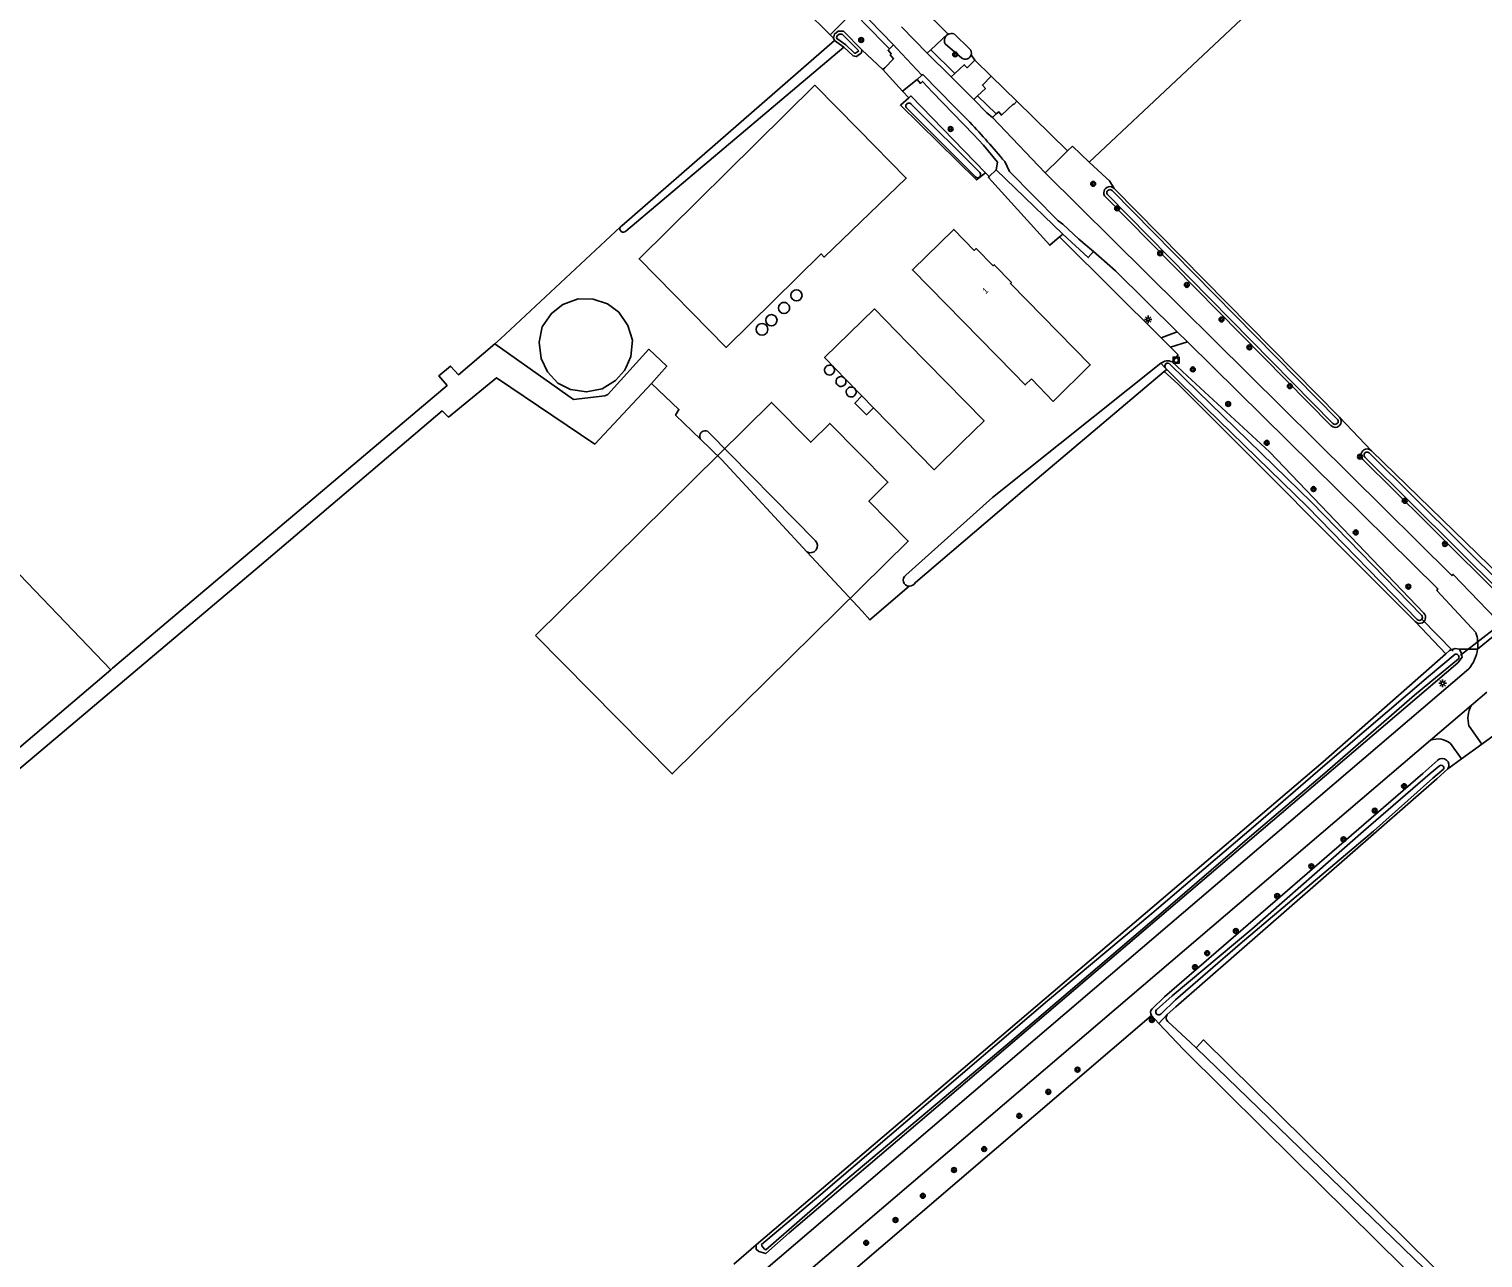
# Model space of a CAD drawing. Extents: x 141000 to 143000, y 400580 to 403500.
# Drawn here: x 142087.7 to 142326.5, y 402801.5 to 403003.4 of the extents above; entities that cross this region are included whole.
import ezdxf

# ---------------------------------------------------------------- set-up
doc = ezdxf.new("R2010")
doc.units = 0
for name, color, linetype in [('gg-afsc-erfafscheiding', 7, 'Continuous'), ('gg-anno-huisnummerreeks BGT', 7, 'Continuous'), ('gg-bbg-bijgebouw', 7, 'Continuous'), ('gg-bbg-gedigitaliseerde bijgebouw', 7, 'Continuous'), ('gg-bbg-hoofdgebouw', 7, 'Continuous'), ('gg-bbg-luifel en loopbrug', 7, 'Continuous'), ('gg-bbg-overig bouwwerk', 7, 'Continuous'), ('gg-knt-bronhoudergrens', 7, 'Continuous'), ('gg-knt-onverhard', 7, 'Continuous'), ('gg-knt-verharding', 7, 'Continuous'), ('gg-knt-verharding nz', 7, 'Continuous'), ('gg-kntw-bovenkant insteek waterloop', 7, 'Continuous'), ('gg-kntw-waterlijn', 7, 'Continuous'), ('gg-kwrk-duiker nz buis', 7, 'Continuous'), ('gt-bbg-plantopografie pand', 7, 'Continuous'), ('gt-grn-groengrens', 7, 'Continuous'), ('gt-grn-vlakafsluiter', 7, 'Continuous'), ('gt-grn-weggrens', 7, 'Continuous'), ('gt-symb-boom', 7, 'Continuous'), ('gt-symb-lichtmast', 7, 'Continuous'), ('gt-symb-rioolschacht', 7, 'Continuous')]:
    doc.layers.add(name, color=color, linetype=linetype)

# ---------------------------------------------------------------- blocks, each defined once
blk = doc.blocks.new('gt0-LMAST')
at = {"layer": 'gt-symb-lichtmast'}
for p, q in [((-0.18, 0.17), (-0.45, 0.44)), ((-0.01, 0.25), (-0.01, 0.62)), ((0.17, 0.17), (0.44, 0.44)), ((-0.26, 0), (-0.63, 0)), ((-0.18, -0.18), (-0.45, -0.45)), ((-0.01, -0.25), (-0.01, -0.63)), ((0.44, -0.45), (0.17, -0.18)), ((0.24, 0), (0.62, 0))]:
    blk.add_line(p, q, dxfattribs=at)
blk.add_circle((-0.01, 0), 0.25, dxfattribs=at)
blk = doc.blocks.new('gt0-BOOM')
at = {"layer": 'gt-symb-boom'}
for radius in [0.4, 0.2]:
    blk.add_circle((0, 0), radius, dxfattribs=at)
blk = doc.blocks.new('gt0-RS')
at = {"layer": 'gt-symb-rioolschacht'}
blk.add_lwpolyline([(-0.5, -0.5), (0.5, -0.5), (0.5, 0.5), (-0.5, 0.5)], close=True, dxfattribs=at)
blk.add_circle((0, 0), 0.375, dxfattribs=at)

msp = doc.modelspace()

# ---------------------------------------------------------------- linework, layer by layer
at = {"layer": 'gg-afsc-erfafscheiding'}
for p, q in [((142227.95, 402996.74), (142224.5, 403000.01)), ((142232.21, 402992.13), (142231.16, 402993.21)), ((142245.42, 402979.18), (142244.82, 402979.8))]:
    msp.add_line(p, q, dxfattribs=at)
for points in [[(142273.63, 402952.69), (142257.5, 402968.7), (142256.97, 402969.25)], [(142275.46, 402948.72), (142276.43, 402949.86), (142275.17, 402951.14)]]:
    msp.add_lwpolyline(points, dxfattribs=at)
at = {"layer": 'gg-bbg-bijgebouw'}
msp.add_line((142224.5, 402943.13), (142226.39, 402941.2), dxfattribs=at)
for points in [[(142223.91, 402986.92), (142231.78, 402978.93), (142218.31, 402965.95), (142217.8, 402966.46), (142202.21, 402951.11), (142187.87, 402965.68), (142216.78, 402994.16), (142223.91, 402986.92)], [(142226.39, 402941.2), (142236.35, 402931), (142240.98, 402935.53), (142244.55, 402939.02), (142231.99, 402951.88), (142226.57, 402957.43), (142218.37, 402949.42), (142223.78, 402943.87), (142224.5, 402943.13)]]:
    msp.add_lwpolyline(points, dxfattribs=at)
at = {"layer": 'gg-bbg-gedigitaliseerde bijgebouw'}
for points in [[(142171.79, 402949.27), (142171.45, 402951.97), (142171.94, 402954.5), (142173.47, 402956.69), (142175.35, 402958.18), (142177.9, 402959.07), (142180.32, 402959.05), (142182.72, 402958.28), (142184.55, 402956.9), (142186.05, 402954.73), (142186.8, 402952.28), (142186.55, 402949.6), (142185.74, 402947.88)], [(142181.8, 402944.31), (142179.27, 402943.79), (142176.61, 402944.18), (142174.54, 402945.24), (142172.85, 402947.07), (142171.79, 402949.27)], [(142181.8, 402944.31), (142183.99, 402945.68), (142185.48, 402947.33), (142185.74, 402947.88)]]:
    msp.add_lwpolyline(points, dxfattribs=at)
at = {"layer": 'gg-bbg-hoofdgebouw'}
msp.add_lwpolyline([(142252.33, 402945.92), (142255.92, 402942.22), (142262.01, 402948.23), (142248.88, 402961.62), (142249.04, 402961.78), (142246.24, 402964.67), (142246.08, 402964.52), (142243.24, 402967.34), (142242.95, 402967.05), (142239.61, 402970.5), (142232.78, 402963.87), (142249.42, 402946.94), (142251.32, 402944.95), (142252.33, 402945.92)], dxfattribs=at)
at = {"layer": 'gg-bbg-luifel en loopbrug'}
msp.add_lwpolyline([(142224.5, 402943.13), (142223.33, 402941.97), (142225.22, 402940.05), (142226.39, 402941.2)], dxfattribs=at)
at = {"layer": 'gg-bbg-overig bouwwerk'}
for centre, radius, start, end in [((142213.74, 402959.65), 0.917, 135.044, 314.956), ((142213.74, 402959.65), 0.917, 315.044, 134.956), ((142211.69, 402957.57), 0.917, 135.0221, 315.0221), ((142211.69, 402957.57), 0.917, 315.0219, 135.0223), ((142209.62, 402955.57), 0.922, 135, 315), ((142209.62, 402955.57), 0.922, 315.0438, 134.9562), ((142208.08, 402954.07), 0.954, 135, 315), ((142208.08, 402954.07), 0.954, 314.9575, 135.0425), ((142219.17, 402947.38), 0.818, 93.7557, 273.8119), ((142219.17, 402947.38), 0.818, 273.7602, 93.8075), ((142221.05, 402945.5), 0.818, 93.7512, 273.8164), ((142221.05, 402945.5), 0.818, 273.8117, 93.7559), ((142222.72, 402943.78), 0.818, 138.7544, 318.8277), ((142222.72, 402943.78), 0.818, 318.781, 138.801)]:
    msp.add_arc(centre, radius, start, end, dxfattribs=at)
at = {"layer": 'gg-knt-bronhoudergrens'}
for p, q in [((142215.06, 403006.63), (142219.28, 403002.43)), ((142219.28, 403002.43), (142219.81, 403001.91)), ((142101.08, 402898.11), (142009.26, 402994.01)), ((142261.85, 402981.56), (142259.09, 402984.18)), ((142265.14, 402978.45), (142265.94, 402977.22)), ((142308.19, 402934.13), (142302.97, 402939.64)), ((142315.37, 402906.05), (142320.4, 402900.74)), ((142328.97, 402887.85), (142326.36, 402885.95)), ((142320.76, 402881.88), (142323.02, 402883.52)), ((142272.08, 402841.33), (142221.14, 402797.79)), ((142203.46, 402800.52), (142207.1, 402803.67))]:
    msp.add_line(p, q, dxfattribs=at)
for points in [[(142210.84, 403030.92), (142245.72, 403061.99), (142292.19, 403010.09), (142261.85, 402981.56)], [(142261.85, 402981.56), (142264.62, 402978.94), (142265.14, 402978.45)], [(142164.17, 402951.7), (142165.12, 402952.51), (142184.82, 402970.89)], [(142164.17, 402951.7), (142158.23, 402946.6), (142156.89, 402948.03), (142154.99, 402946.45), (142156.33, 402944.86), (142101.4, 402898.39), (142101.08, 402898.11)], [(142164.17, 402951.7), (142177.12, 402942.53), (142182.26, 402943.17), (142182.75, 402943.39), (142189.47, 402950.79), (142192.43, 402948.01), (142189.91, 402945.16)], [(142024.33, 402840.61), (142022.47, 402838.91), (142028.48, 402832.9), (142040.38, 402843.06), (142064.01, 402863.29), (142090.33, 402885.42), (142125.51, 402915.15), (142155.54, 402940.68), (142156.57, 402939.65), (142164.47, 402946.13), (142180.6, 402935.22), (142189.91, 402945.16)], [(142189.91, 402945.16), (142194.43, 402940.93), (142193.88, 402939.99), (142197.98, 402936.02)], [(142215.46, 402917.5), (142224.55, 402907.77), (142225.81, 402906.35), (142232.25, 402911.88)], [(142101.08, 402898.11), (142028.36, 402836.3), (142024.33, 402840.61)], [(142368.96, 402748.16), (142369.92, 402749.18), (142351.54, 402767.36), (142280.62, 402837.33), (142279.39, 402836.06)]]:
    msp.add_lwpolyline(points, dxfattribs=at)
at = {"layer": 'gg-knt-onverhard'}
for p, q in [((142223.1, 403006.27), (142219.28, 403002.43)), ((142323.02, 402883.52), (142326.36, 402885.95))]:
    msp.add_line(p, q, dxfattribs=at)
at = {"layer": 'gg-knt-verharding'}
for p, q in [((142223.78, 403006.91), (142229.69, 403000.79)), ((142235.23, 402999.43), (142230.98, 403003.74)), ((142239.15, 402995.54), (142235.23, 402999.43)), ((142239.73, 402996.11), (142235.81, 403000)), ((142227.95, 402996.74), (142228.27, 402997.05)), ((142231.16, 402993.21), (142227.95, 402996.74)), ((142233.58, 402995.11), (142231.16, 402993.21)), ((142242.86, 402991.82), (142239.15, 402995.54)), ((142246.56, 402989.46), (142243.46, 402992.42)), ((142254.62, 402979.79), (142245.96, 402988.85)), ((142258.27, 402983.38), (142259.09, 402984.18)), ((142246.54, 402980.26), (142245.42, 402979.18)), ((142257.52, 402969.72), (142256.97, 402969.25)), ((142266.14, 402963.68), (142276.29, 402953.67)), ((142276.29, 402953.67), (142273.63, 402952.69)), ((142275.17, 402951.14), (142273.63, 402952.69)), ((142276.29, 402953.67), (142277.97, 402952.02)), ((142277.97, 402952.02), (142275.17, 402951.14)), ((142324.18, 402898.3), (142206.08, 402797.45)), ((142324.59, 402892.27), (142327.18, 402894.49)), ((142324.23, 402888.87), (142326.36, 402885.95)), ((142209.61, 402794.18), (142317.92, 402886.59)), ((142323.02, 402883.52), (142321.19, 402886.04))]:
    msp.add_line(p, q, dxfattribs=at)
for points in [[(142229.05, 403000.17), (142224.8, 403004.45), (142223.1, 403006.27)], [(142234.34, 402995.84), (142230.24, 403000.23), (142229.69, 403000.79)], [(142235.81, 403000), (142237.64, 403001.68), (142238.61, 403002.64)], [(142228.27, 402997.05), (142229.7, 402998.51), (142229.14, 402999.14), (142229.31, 402999.35), (142228.79, 402999.92), (142229.05, 403000.17)], [(142239.73, 402996.11), (142241.3, 402997.53), (142241.8, 402997.05), (142243.04, 402998.31)], [(142242.23, 402988.08), (142239.77, 402990.55), (142234.49, 402995.93), (142234.34, 402995.84)], [(142243.46, 402992.42), (142244.77, 402993.64), (142244.3, 402994.2), (142245.74, 402995.66)], [(142246.54, 402980.26), (142246.74, 402981.56), (142244.48, 402984.31), (142242.83, 402986.08), (142236.09, 402993.04), (142234.42, 402994.79), (142234.1, 402994.47), (142233.58, 402995.11)], [(142242.86, 402991.82), (142245.01, 402989.66), (142245.96, 402988.85)], [(142246.56, 402989.46), (142247.01, 402989.78), (142247.4, 402989.27), (142249.35, 402991.08), (142249.45, 402991.01), (142249.96, 402991.53)], [(142262.53, 402966.84), (142260.14, 402968.88), (142257.5, 402971.34), (142256.73, 402971.91), (142248.73, 402979.98), (142247.95, 402981.62)], [(142254.62, 402979.79), (142256.99, 402982.13), (142258.27, 402983.38)], [(142256.97, 402969.25), (142255.35, 402967.88), (142245.27, 402979.03), (142245.42, 402979.18)], [(142330.02, 402905.09), (142321.65, 402913.8), (142321.43, 402913.61), (142254.62, 402979.79)], [(142262.53, 402966.84), (142261.67, 402965.86), (142257.52, 402969.72)], [(142266.14, 402963.68), (142263.43, 402966.08), (142262.53, 402966.84)], [(142277.97, 402952.02), (142319.13, 402911.42), (142318.96, 402911.17), (142325.38, 402904.2)]]:
    msp.add_lwpolyline(points, dxfattribs=at)
for centre, radius, start, end in [((142147.78, 402898.63), 130.08, 39.6422, 43.4452), ((142319.51, 402902.32), 6.16, 352.7594, 17.7772), ((142319.51, 402902.32), 6.16, 319.2711, 352.7448), ((142328.67, 402890.13), 4.62, 152.3265, 195.7818), ((142319.06, 402883.36), 3.42, 51.4883, 109.4163)]:
    msp.add_arc(centre, radius, start, end, dxfattribs=at)
at = {"layer": 'gg-knt-verharding nz'}
for p, q in [((142229.05, 403000.17), (142229.69, 403000.79)), ((142235.81, 403000), (142235.23, 402999.43)), ((142234.34, 402995.84), (142233.58, 402995.11)), ((142239.15, 402995.54), (142239.73, 402996.11)), ((142243.46, 402992.42), (142242.86, 402991.82)), ((142245.96, 402988.85), (142246.56, 402989.46)), ((142317.92, 402886.59), (142324.59, 402892.27))]:
    msp.add_line(p, q, dxfattribs=at)
at = {"layer": 'gg-kntw-bovenkant insteek waterloop'}
for p, q in [((142185.73, 402970.18), (142221.52, 403000.43)), ((142219.97, 403001.52), (142219.81, 403001.91)), ((142238.17, 403000.97), (142240.91, 402998.61)), ((142242.22, 403000.12), (142239.62, 403002.59)), ((142302.97, 402939.64), (142265.94, 402977.22)), ((142301.52, 402938.26), (142264.52, 402975.82)), ((142216.84, 402919.35), (142199.31, 402937.2)), ((142272.08, 402841.33), (142273.27, 402840.06))]:
    msp.add_line(p, q, dxfattribs=at)
for points in [[(142224.5, 403000.01), (142221.45, 403003.04), (142220.58, 403003.06), (142219.98, 403002.57), (142219.81, 403001.91)], [(142184.82, 402970.89), (142184.92, 402971.01), (142185.05, 402971.1), (142219.97, 403001.52)], [(142221.52, 403000.43), (142223.04, 402999), (142223.58, 402998.89), (142224.42, 402999.5), (142224.5, 403000.01)], [(142244.82, 402979.8), (142243.34, 402978.63), (142230.81, 402990.89), (142232.21, 402992.13)], [(142244.82, 402979.8), (142232.54, 402992.42), (142232.21, 402992.13)], [(142231.71, 402913.67), (142245.97, 402926.47), (142273.61, 402948.5)], [(142275.46, 402948.72), (142277.9, 402946.45), (142291.44, 402933.96), (142316.8, 402907.45)], [(142233.28, 402912.5), (142250.82, 402927.41), (142274.15, 402947.15)], [(142274.15, 402947.15), (142276.37, 402945.1), (142315.37, 402906.05)], [(142197.98, 402936.02), (142201.48, 402932.63), (142215.46, 402917.5)], [(142333.37, 402910.48), (142332.84, 402910.5), (142332.22, 402910.75), (142331.43, 402911.54), (142308.19, 402934.13)], [(142331.1, 402908.56), (142317.19, 402922.38), (142306.78, 402932.71)], [(142322.68, 402901.52), (142323.02, 402900.84), (142323.09, 402900.24), (142322.38, 402899.26), (142266.3, 402851.46), (142212.55, 402805.67), (142208.68, 402802.25), (142207.57, 402802.57), (142207.11, 402802.95), (142207.1, 402803.67)], [(142207.1, 402803.67), (142300.27, 402883.03), (142320.4, 402900.74)], [(142322.68, 402901.52), (142321.96, 402901.63), (142321.03, 402901.29), (142320.4, 402900.74)], [(142319.08, 402883.32), (142316.66, 402881.08), (142274.22, 402844.4), (142272.17, 402842.44)], [(142274.65, 402841.52), (142276.07, 402842.77), (142318.93, 402880.24), (142320.76, 402881.88)], [(142369.74, 402743.71), (142350.81, 402762.53), (142341.22, 402772.59), (142290.46, 402822.73), (142277.32, 402835.78), (142273.27, 402840.06)], [(142279.39, 402836.06), (142278.49, 402836.93), (142274.73, 402840.35)], [(142368.96, 402748.16), (142316.88, 402799.79), (142279.39, 402836.06)]]:
    msp.add_lwpolyline(points, dxfattribs=at)
for centre, radius, start, end in [((142239.19, 403001.51), 1.16, 115.2443, 207.7556), ((142239.19, 403001.51), 1.16, 68.5981, 115.2785), ((142241.47, 402999.44), 1.01, 236.0969, 344.7533), ((142241.47, 402999.44), 1.01, 344.721, 42.1462), ((142265.23, 402976.52), 1, 44.5737, 224.5757), ((142185.31, 402970.59), 0.575, 148.5333, 315.7431), ((142274.71, 402947.22), 1.68, 63.2536, 130.5467), ((142302.23, 402938.96), 1, 224.5887, 42.3719), ((142198.75, 402936.49), 0.897, 171.7459, 211.3911), ((142198.75, 402936.49), 0.903, 51.5344, 171.8646), ((142307.48, 402933.42), 1, 45.2422, 225.244), ((142216.01, 402918.53), 1.17, 242.0828, 44.593), ((142232.26, 402912.86), 0.979, 124.2668, 269.3432), ((142232.32, 402912.93), 1.05, 265.9035, 335.663), ((142316.09, 402906.75), 1, 224.2302, 44.2302), ((142319.8, 402882.47), 1.12, 328.3027, 130.5284), ((142272.68, 402841.84), 0.786, 130.599, 220.183), ((142275.41, 402840.98), 0.93, 144.711, 222.5518)]:
    msp.add_arc(centre, radius, start, end, dxfattribs=at)
at = {"layer": 'gg-kntw-waterlijn'}
for p, q in [((142221.52, 403000.43), (142219.97, 403001.52)), ((142243.85, 402979.82), (142232.57, 402991.09)), ((142231.86, 402990.39), (142243.14, 402979.11)), ((142265.58, 402976.87), (142302.59, 402939.31)), ((142264.87, 402976.17), (142301.88, 402938.61)), ((142274.15, 402947.15), (142274.57, 402947.5))]:
    msp.add_line(p, q, dxfattribs=at)
for points in [[(142221.83, 403000.82), (142223.28, 402999.46), (142223.46, 402999.42), (142223.95, 402999.78), (142223.96, 402999.84), (142221.24, 403002.55), (142220.75, 403002.56), (142220.43, 403002.29), (142220.34, 403001.94), (142220.38, 403001.84), (142221.83, 403000.82)], [(142274.35, 402947.72), (142274.22, 402947.85), (142273.61, 402948.5)], [(142316.44, 402907.1), (142298.39, 402925.64), (142277.54, 402945.92), (142275.1, 402948.37)], [(142274.57, 402947.5), (142276.84, 402945.21), (142297.68, 402924.93), (142315.73, 402906.4)], [(142307.84, 402933.77), (142330.28, 402911.51), (142331.58, 402910.17), (142332.25, 402909.53)], [(142307.13, 402933.06), (142329.57, 402910.81), (142331.48, 402908.89)], [(142272.14, 402858.13), (142254.96, 402843.75), (142217.74, 402811.94), (142208.01, 402803.73), (142208.05, 402803.51), (142208.25, 402803.22), (142208.51, 402802.94), (142208.73, 402802.88), (142221.49, 402813.97), (142248.33, 402836.6), (142273.23, 402857.77), (142288.17, 402870.65), (142300.54, 402881.14), (142315.26, 402893.95), (142322.48, 402899.97), (142322.59, 402900.14), (142322.52, 402900.48), (142322.29, 402900.71), (142321.94, 402900.71), (142317.59, 402897.03), (142300.22, 402882.19), (142289.2, 402872.65), (142272.14, 402858.13)], [(142319.37, 402882.38), (142317.87, 402881.08), (142306.92, 402871.64), (142288.57, 402855.54), (142275.47, 402844.59), (142272.88, 402842.27)], [(142273.63, 402841.61), (142275.99, 402843.9), (142286.64, 402853.12), (142308.51, 402871.66), (142318.26, 402880.34), (142320.04, 402881.81)], [(142273.27, 402840.06), (142273.93, 402840.76), (142274.65, 402841.52)]]:
    msp.add_lwpolyline(points, dxfattribs=at)
for centre, radius, start, end in [((142232.21, 402990.74), 0.5, 44.9991, 225.0009), ((142243.49, 402979.46), 0.5, 225, 45), ((142265.23, 402976.52), 0.5, 44.5934, 224.5962), ((142274.74, 402948.03), 0.5, 43.9817, 217.6445), ((142302.23, 402938.96), 0.5, 224.5916, 44.598), ((142307.48, 402933.42), 0.5, 45.2408, 225.2454), ((142316.09, 402906.75), 0.5, 224.2335, 44.228), ((142319.64, 402882.02), 0.447, 332.5549, 126.6709), ((142273.26, 402841.94), 0.5, 138.6582, 277.321), ((142273.26, 402841.94), 0.499, 277.0296, 318.6979)]:
    msp.add_arc(centre, radius, start, end, dxfattribs=at)
at = {"layer": 'gg-kwrk-duiker nz buis'}
for p, q in [((142322.84, 402900.57), (142333.04, 402908.51)), ((142316.45, 402906.52), (142321.61, 402901.23))]:
    msp.add_line(p, q, dxfattribs=at)
at = {"layer": 'gt-bbg-plantopografie pand'}
msp.add_lwpolyline([(142170.86, 402903.78), (142209.64, 402942.06), (142216.08, 402935.53), (142219.22, 402938.62), (142228.76, 402928.95), (142225.63, 402925.86), (142232.1, 402919.3), (142193.32, 402881.03), (142170.86, 402903.78)], dxfattribs=at)
at = {"layer": 'gt-grn-groengrens'}
for p, q in [((142238.61, 403002.64), (142238.7, 403002.55)), ((142249.96, 402991.53), (142245.74, 402995.66)), ((142325.62, 402901.54), (142322.68, 402901.52))]:
    msp.add_line(p, q, dxfattribs=at)
at = {"layer": 'gt-grn-vlakafsluiter'}
for p, q in [((142238.61, 403002.64), (142234.12, 403007.04)), ((142243.04, 402998.31), (142242.45, 402999.18)), ((142245.74, 402995.66), (142243.04, 402998.31)), ((142249.96, 402991.53), (142258.27, 402983.38)), ((142257.52, 402969.72), (142246.54, 402980.26)), ((142274.57, 402947.5), (142274.35, 402947.72))]:
    msp.add_line(p, q, dxfattribs=at)
at = {"layer": 'gt-grn-weggrens'}
msp.add_line((142330.02, 402905.09), (142325.62, 402901.54), dxfattribs=at)

# ---------------------------------------------------------------- block references
at = {"layer": 'gt-symb-boom'}
for p in [(142224.36, 403001.6), (142239.81, 402999.24), (142239.06, 402986.99), (142262.49, 402977.98), (142266.42, 402973.94), (142273.49, 402966.55), (142277.86, 402961.37), (142283.56, 402955.68), (142288.15, 402951.12), (142278.86, 402947.49), (142294.79, 402944.73), (142284.67, 402941.81), (142291, 402935.42), (142306.32, 402933.15), (142298.69, 402927.83), (142313.67, 402925.91), (142305.62, 402920.71), (142320.27, 402918.8), (142314.26, 402911.81), (142313.56, 402879.02), (142308.74, 402875.01), (142303.6, 402870.3), (142298.33, 402865.87), (142292.72, 402860.99), (142285.91, 402855.23), (142281.21, 402851.59), (142279.22, 402849.29), (142272.13, 402840.62), (142259.91, 402832.46), (142255.11, 402828.8), (142250.34, 402824.88), (142244.58, 402819.41), (142239.62, 402815.98), (142234.49, 402811.73), (142230, 402807.75), (142225.2, 402804)]:
    msp.add_blockref('gt0-BOOM', p, dxfattribs=at)
at = {"layer": 'gt-symb-lichtmast'}
for p in [(142271.52, 402955.7), (142319.91, 402895.92)]:
    msp.add_blockref('gt0-LMAST', p, dxfattribs=at)
at = {"layer": 'gt-symb-rioolschacht'}
msp.add_blockref('gt0-RS', (142276.11, 402949.01), dxfattribs=at)

# ---------------------------------------------------------------- texts
at = {"layer": 'gg-anno-huisnummerreeks BGT'}
msp.add_text('1', height=1, rotation=44.1, dxfattribs=at).set_placement((142244.84, 402959.81))

doc.saveas('drawing.dxf')
